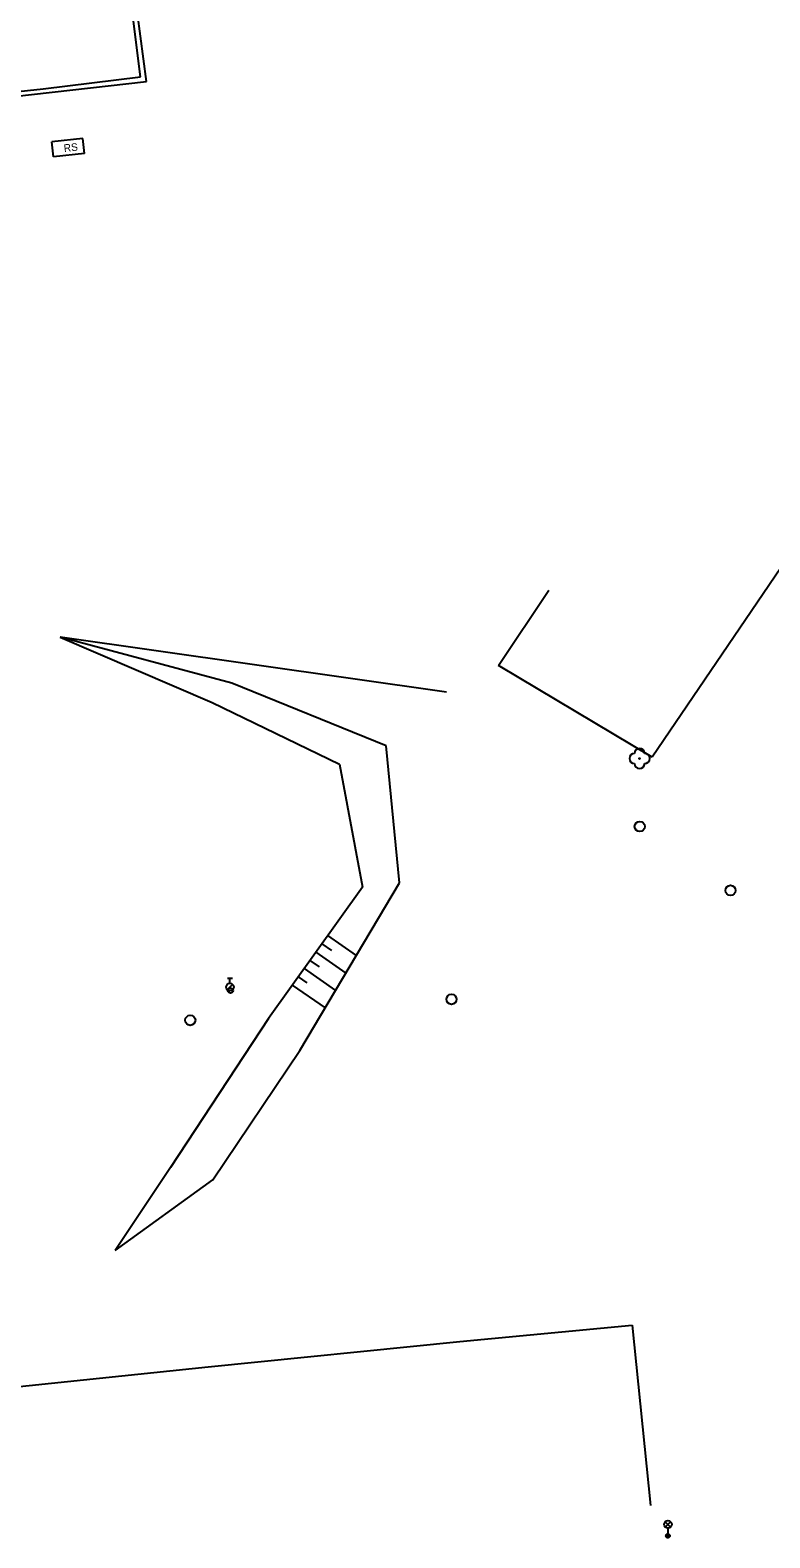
# Model space of a CAD drawing. Extents: x -539694 to -539148, y -1156467 to -1155920.
# Drawn here: x -539458.4 to -539385.3, y -1156271.6 to -1156122.8 of the extents above; entities that cross this region are included whole.
import ezdxf

# ---------------------------------------------------------------- set-up
doc = ezdxf.new("R2010")
doc.units = 0
for name, color, linetype in [('Vrstva 11', 7, 'Continuous'), ('Vrstva 14', 7, 'Continuous'), ('Vrstva 15', 7, 'Continuous'), ('Vrstva 22', 7, 'Continuous'), ('Vrstva 27', 7, 'Continuous'), ('Vrstva 28', 7, 'Continuous'), ('Vrstva 33', 7, 'Continuous'), ('Vrstva 41', 7, 'Continuous'), ('Vrstva 5', 7, 'Continuous'), ('Vrstva 7', 7, 'Continuous')]:
    doc.layers.add(name, color=color, linetype=linetype)

msp = doc.modelspace()

# ---------------------------------------------------------------- linework, layer by layer
at = {"layer": 'Vrstva 11'}
for p, q in [((-539447.46, -1156127.42), (-539448.25, -1156121.12)), ((-539446.87, -1156127.88), (-539447.76, -1156121.17)), ((-539473.24, -1156130.82), (-539446.87, -1156127.88)), ((-539465.24, -1156129.46), (-539457.07, -1156128.59)), ((-539457.07, -1156128.59), (-539447.46, -1156127.42))]:
    msp.add_line(p, q, dxfattribs=at)
at = {"layer": 'Vrstva 14'}
for p, q in [((-539438.46, -1156187.23), (-539455.4, -1156182.71)), ((-539455.4, -1156182.71), (-539440.39, -1156189.14)), ((-539423.19, -1156193.44), (-539438.46, -1156187.23)), ((-539440.39, -1156189.14), (-539427.82, -1156195.23)), ((-539421.9, -1156206.94), (-539423.19, -1156193.44)), ((-539427.82, -1156195.23), (-539425.55, -1156207.36)), ((-539425.55, -1156207.36), (-539434.84, -1156220.32)), ((-539431.72, -1156223.49), (-539421.9, -1156206.94)), ((-539434.84, -1156220.32), (-539444.52, -1156235.04)), ((-539440.32, -1156236.26), (-539431.72, -1156223.49)), ((-539444.52, -1156235.04), (-539449.96, -1156243.23)), ((-539449.96, -1156243.23), (-539440.32, -1156236.26))]:
    msp.add_line(p, q, dxfattribs=at)
at = {"layer": 'Vrstva 15'}
for p, q in [((-539429.571, -1156212.97), (-539428.613, -1156213.636)), ((-539428.988, -1156212.157), (-539426.162, -1156214.123)), ((-539430.736, -1156214.595), (-539429.824, -1156215.23)), ((-539430.154, -1156213.782), (-539427.185, -1156215.847)), ((-539431.902, -1156216.221), (-539431.034, -1156216.825)), ((-539431.319, -1156215.408), (-539428.209, -1156217.572)), ((-539432.484, -1156217.034), (-539429.232, -1156219.297))]:
    msp.add_line(p, q, dxfattribs=at)
at = {"layer": 'Vrstva 22'}
msp.add_circle((-539398.17, -1156194.68), 0.05, dxfattribs=at)
for centre, start, end in [((-539398.17, -1156194.18), 0, 180), ((-539398.67, -1156194.68), 90, 270), ((-539398.17, -1156195.18), 180, 0), ((-539397.67, -1156194.68), 270, 90)]:
    msp.add_arc(centre, 0.5, start, end, dxfattribs=at)
at = {"layer": 'Vrstva 27'}
for centre in [(-539398.16, -1156201.39), (-539389.19, -1156207.69), (-539416.75, -1156218.44), (-539442.55, -1156220.51)]:
    msp.add_circle(centre, 0.5, dxfattribs=at)
at = {"layer": 'Vrstva 28'}
for p, q in [((-539438.89, -1156216.355), (-539438.39, -1156216.355)), ((-539438.64, -1156216.855), (-539438.64, -1156216.355)), ((-539438.898, -1156217.502), (-539438.368, -1156216.972))]:
    msp.add_line(p, q, dxfattribs=at)
for centre, radius in [((-539438.64, -1156217.23), 0.375), ((-539438.58, -1156217.58), 0.25)]:
    msp.add_circle(centre, radius, dxfattribs=at)
at = {"layer": 'Vrstva 33'}
for p, q in [((-539395.644, -1156270.521), (-539395.116, -1156269.991)), ((-539395.644, -1156269.991), (-539395.116, -1156270.521)), ((-539395.38, -1156270.63), (-539395.38, -1156271.38))]:
    msp.add_line(p, q, dxfattribs=at)
for centre, radius in [((-539395.38, -1156270.256), 0.375), ((-539395.38, -1156271.381), 0.2), ((-539395.38, -1156271.381), 0.145), ((-539395.38, -1156271.381), 0.0876)]:
    msp.add_circle(centre, radius, dxfattribs=at)
at = {"layer": 'Vrstva 5'}
for p, q in [((-539453.155, -1156133.488), (-539456.218, -1156133.819)), ((-539456.062, -1156135.314), (-539456.218, -1156133.819)), ((-539452.999, -1156134.983), (-539453.155, -1156133.488)), ((-539452.999, -1156134.983), (-539456.062, -1156135.314))]:
    msp.add_line(p, q, dxfattribs=at)
at = {"layer": 'Vrstva 7'}
for p, q in [((-539378.22, -1156167.03), (-539396.93, -1156194.53)), ((-539412.12, -1156185.51), (-539407.122, -1156178.077)), ((-539417.25, -1156188.13), (-539455.4, -1156182.71)), ((-539396.93, -1156194.53), (-539412.12, -1156185.51)), ((-539415.94, -1156252.2), (-539398.92, -1156250.59)), ((-539398.92, -1156250.59), (-539397.09, -1156268.4)), ((-539440.78, -1156254.69), (-539415.94, -1156252.2)), ((-539460.044, -1156256.71), (-539440.78, -1156254.69))]:
    msp.add_line(p, q, dxfattribs=at)

# ---------------------------------------------------------------- texts
at = {"layer": 'Vrstva 41'}
msp.add_text('RS', height=0.75, rotation=6.16768, dxfattribs=at).set_placement((-539455.008, -1156134.832))

doc.saveas('drawing.dxf')
